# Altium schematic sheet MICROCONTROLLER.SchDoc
size A4; SheetNumber: 2; SheetTotal: 4
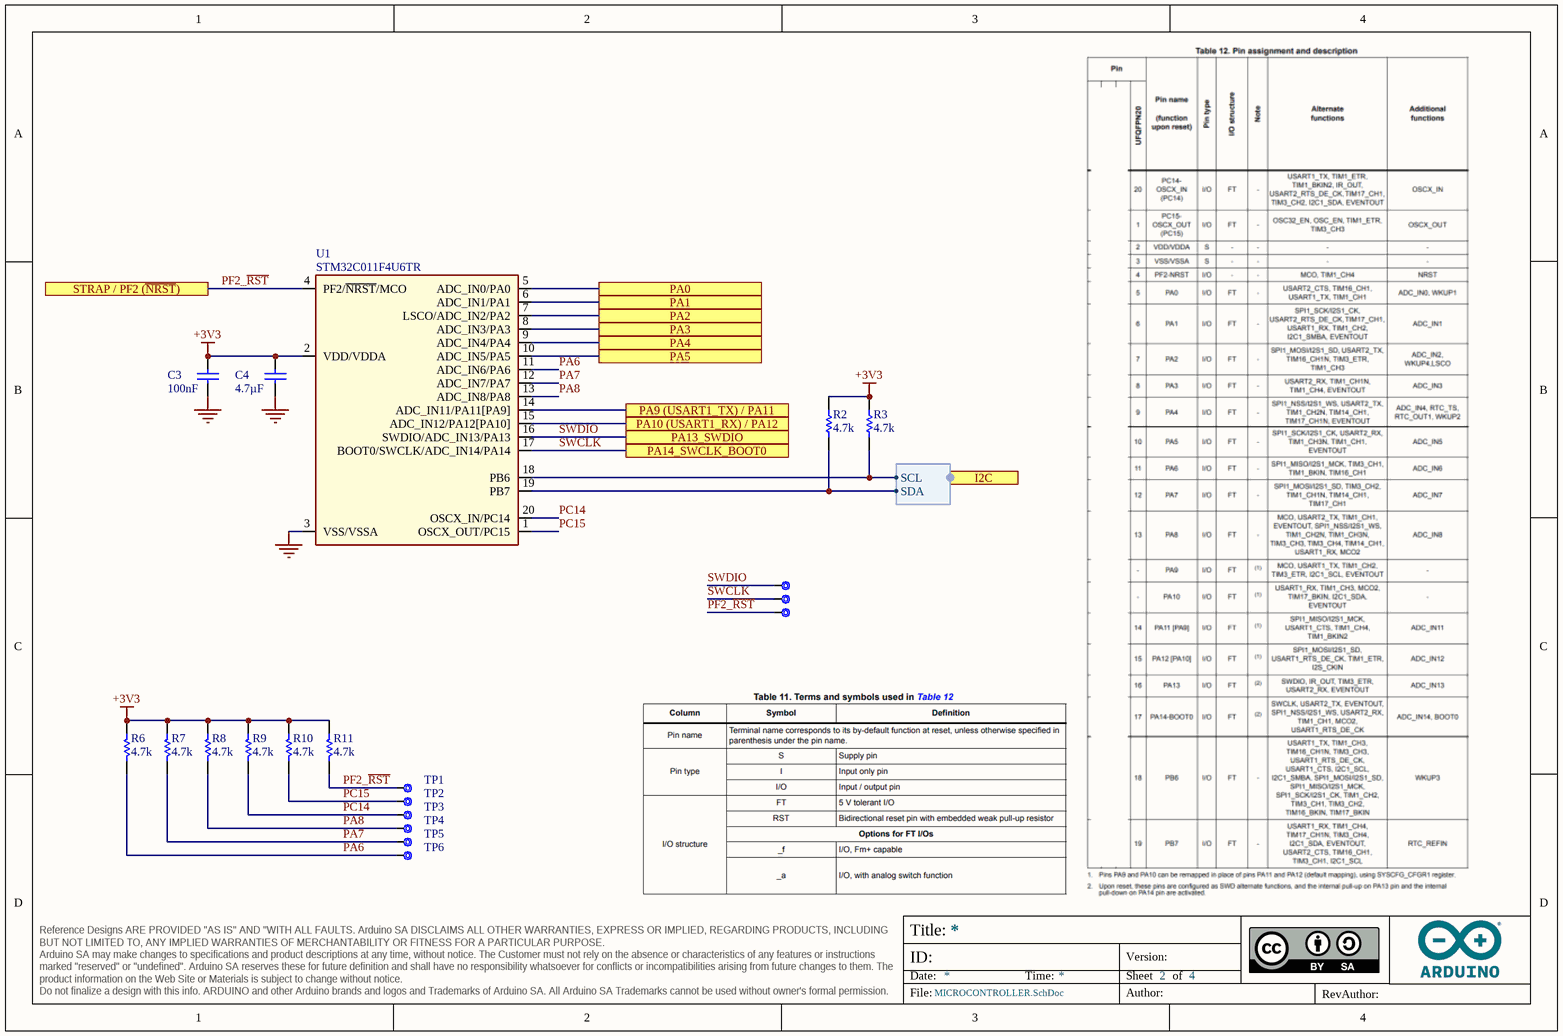
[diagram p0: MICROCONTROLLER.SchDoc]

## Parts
C3  value 100nF  [CAP-0402]  (hidden comment: 0402B104K160CT)
C4  value 4.7µF  [CAP-0603]  (hidden comment: GRM188R61C475KAAJD)
R2  value 4.7k  [RES-0402]  (hidden comment: RC0402FR-074K7L)
R3  value 4.7k  [RES-0402]  (hidden comment: RC0402FR-074K7L)
R6  value 4.7k  [RES-0402]  (hidden comment: RC0402FR-074K7L)
R7  value 4.7k  [RES-0402]  (hidden comment: RC0402FR-074K7L)
R8  value 4.7k  [RES-0402]  (hidden comment: RC0402FR-074K7L)
R9  value 4.7k  [RES-0402]  (hidden comment: RC0402FR-074K7L)
R10  value 4.7k  [RES-0402]  (hidden comment: RC0402FR-074K7L)
R11  value 4.7k  [RES-0402]  (hidden comment: RC0402FR-074K7L)
TP1  Test point 1.00mm  [TP-1.00MM]  (value not drawn)  (no BOM)
TP2  Test point 1.00mm  [TP-1.00MM]  (value not drawn)  (no BOM)
TP3  Test point 1.00mm  [TP-1.00MM]  (value not drawn)  (no BOM)
TP4  Test point 1.00mm  [TP-1.00MM]  (value not drawn)  (no BOM)
TP5  Test point 1.00mm  [TP-1.00MM]  (value not drawn)  (no BOM)
TP6  Test point 1.00mm  [TP-1.00MM]  (value not drawn)  (no BOM)
TP7  Test point 1.00mm  [TP-1.00MM]  (value not drawn)  (no BOM)
TP8  Test point 1.00mm  [TP-1.00MM]  (value not drawn)  (no BOM)
TP9  Test point 1.00mm  [TP-1.00MM]  (value not drawn)  (no BOM)
U1  STM32C011F4U6TR  [UFQFPN20]

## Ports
I2C (harness I2C), PA0, PA1, PA2, PA3, PA4, PA5, PA9 (USART1_TX) / PA11, PA10 (USART1_RX) / PA12, PA13_SWDIO, PA14_SWCLK_BOOT0, STRAP / PF2 (~{NRST})

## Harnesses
I2C: SDA, SCL

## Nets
+3V3: C3.1 C4.2 R2.2 R3.2 R6.1 R7.1 R8.1 R9.1 R10.1 R11.1 U1.2(VDD/VDDA)
GND: C3.2 C4.1 U1.3(VSS/VSSA)
PA0: U1.5(ADC_IN0/PA0) ; port PA0
PA1: U1.6(ADC_IN1/PA1) ; port PA1
PA2: U1.7(LSCO/ADC_IN2/PA2) ; port PA2
PA3: U1.8(ADC_IN3/PA3) ; port PA3
PA4: U1.9(ADC_IN4/PA4) ; port PA4
PA5: U1.10(ADC_IN5/PA5) ; port PA5
PA6: R6.2 TP6.X U1.11(ADC_IN6/PA6)
PA7: R7.2 TP5.X U1.12(ADC_IN7/PA7)
PA8: R8.2 TP4.X U1.13(ADC_IN8/PA8)
PA9 (USART1_TX) / PA11: U1.14(ADC_IN11/PA11[PA9]) ; port PA9 (USART1_TX) / PA11
PA10 (USART1_RX) / PA12: U1.15(ADC_IN12/PA12[PA10]) ; port PA10 (USART1_RX) / PA12
PC14: R9.2 TP3.X U1.20(OSCX_IN/PC14)
PC15: R10.2 TP2.X U1.1(OSCX_OUT/PC15)
PF2_~{RST}: R11.2 TP1.X TP9.X U1.4(PF2/~{NRST}/MCO) ; port STRAP / PF2 (~{NRST})
SWCLK: TP8.X U1.17(BOOT0/SWCLK/ADC_IN14/PA14) ; port PA14_SWCLK_BOOT0
SWDIO: TP7.X U1.16(SWDIO/ADC_IN13/PA13) ; port PA13_SWDIO
NetR2_1: R2.1 U1.19(PB7) ; port I2C.SDA
NetR3_1: R3.1 U1.18(PB6) ; port I2C.SCL

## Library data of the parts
C3 = C0012-A.15: CAP CHIP 0402 100nF 10% 16V X7R; Manufacturer: Walsin; Code Arduino: 0132
C4 = C0054-A.16: CAP CHIP 0603 4.7uF 10% 16V X5R; Manufacturer: Murata; Code Arduino: A5072
R2 R3 = R0013-A.24: RES CHIP 0402 4k7 1% 1/16W; Manufacturer: YAGEO; Code Arduino: 2196; Power: 62.5mW; Temperature coefficient: 200ppm
R6-R11 = R0013-A.24: RES CHIP 0402 4k7 1% 1/16W; Manufacturer: YAGEO; Power: 62.5mW; Code Arduino: 2196; Temperature coefficient: 200ppm
TP1-TP9 = UT0013-A.5: Manufacturer: This is not a component
U1 = U0363-A.3: IC Cortex M0, 32b MCU, 32KB Flash, 6KB RAM, VDD 2-3.6V, -40°C to 85°C, QFN20 3x3mm; Manufacturer: ST Microelectronics; Code Arduino: U0363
